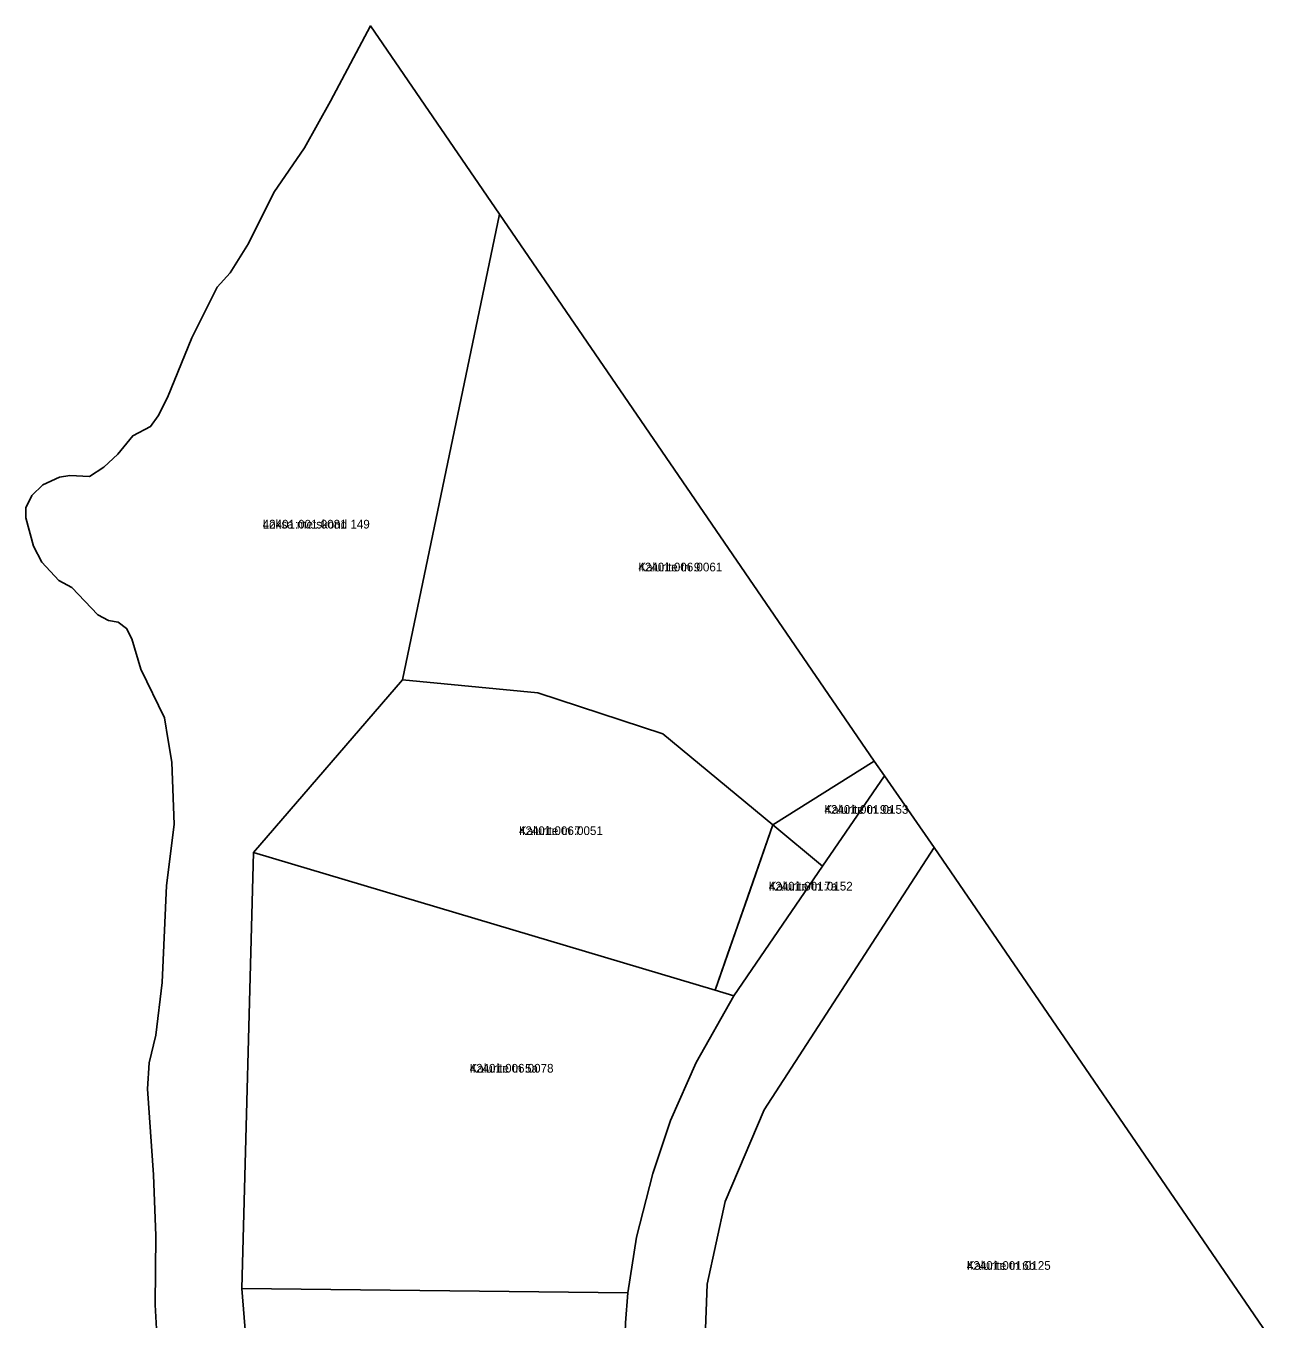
# Model space of a CAD drawing. Extents: x 595979 to 597983, y 6604231 to 6607350.
# Drawn here: x 596332.4 to 596548.3, y 6607126.6 to 6607350 of the extents above; entities that cross this region are included whole.
import ezdxf

# ---------------------------------------------------------------- set-up
doc = ezdxf.new("R2010")
doc.units = 0
for name, color, linetype in [('L_AADRESS', 7, 'Continuous'), ('PIIR', 7, 'Continuous'), ('TUNNUS', 7, 'Continuous')]:
    doc.layers.add(name, color=color, linetype=linetype)

msp = doc.modelspace()

# ---------------------------------------------------------------- linework, layer by layer
at = {"layer": 'PIIR'}
for points in [[(596355.78, 6607109.34), (596354.72, 6607129.05), (596354.85, 6607140.96), (596354.45, 6607151.54), (596353.4, 6607166.36), (596353.66, 6607170.86), (596354.85, 6607175.62), (596355.91, 6607184.75), (596356.65, 6607201.52), (596357.99, 6607212.07), (596357.59, 6607222.8), (596356.97, 6607226.55), (596356.33, 6607230.48), (596352.23, 6607238.88), (596350.69, 6607244.1), (596349.78, 6607245.93), (596348.29, 6607247.03), (596346.65, 6607247.32), (596344.8, 6607248.25), (596340.3, 6607253.01), (596338.05, 6607254.2), (596335.14, 6607257.38), (596333.69, 6607260.16), (596332.36, 6607265.05), (596332.36, 6607266.77), (596333.42, 6607268.89), (596335.27, 6607270.74), (596338.18, 6607272.06), (596339.98, 6607272.35), (596343.34, 6607272.19), (596345.85, 6607273.78), (596348.24, 6607276.03), (596350.83, 6607279.22), (596353.92, 6607280.79), (596355.25, 6607282.65), (596356.84, 6607285.82), (596361.07, 6607296.14), (596365.44, 6607304.87), (596367.68, 6607307.38), (596370.86, 6607312.41), (596375.22, 6607321.27), (596380.52, 6607328.95), (596385.01, 6607337.02), (596391.91, 6607350.04), (596414.22, 6607317.51), (596397.46, 6607237.04), (596371.73, 6607207.23), (596369.69, 6607131.86), (596375.64, 6607058.29)], [(596435.98, 6607125.93), (596436.42, 6607131.12), (596437.91, 6607140.77), (596440.71, 6607151.77), (596443.8, 6607160.91), (596448.2, 6607170.94), (596454.72, 6607182.46), (596470.04, 6607204.83), (596480.75, 6607220.47), (596489.35, 6607208.1), (596459.97, 6607162.74), (596453.22, 6607146.91), (596450.12, 6607132.65), (596449.44, 6607114.1)]]:
    msp.add_lwpolyline(points, dxfattribs=at)
for points in [[(596414.22, 6607317.51), (596479.01, 6607222.97), (596461.48, 6607211.99), (596442.45, 6607227.7), (596420.87, 6607234.78), (596397.46, 6607237.04)], [(596371.73, 6607207.23), (596397.46, 6607237.04), (596420.87, 6607234.78), (596442.45, 6607227.7), (596461.48, 6607211.99), (596451.51, 6607183.42)], [(596461.48, 6607211.99), (596479.01, 6607222.97), (596480.75, 6607220.47), (596470.04, 6607204.83)], [(596454.72, 6607182.46), (596451.51, 6607183.42), (596453.66, 6607189.58), (596457.08, 6607199.38), (596461.48, 6607211.99), (596470.04, 6607204.83)], [(596371.73, 6607207.23), (596451.51, 6607183.42), (596454.72, 6607182.46), (596448.2, 6607170.94), (596443.8, 6607160.91), (596440.71, 6607151.77), (596437.91, 6607140.77), (596436.42, 6607131.12), (596369.69, 6607131.86)], [(596489.35, 6607208.1), (596548.29, 6607122.04), (596541.96, 6607120.71), (596544.58, 6607065.45), (596522.96, 6607062.1), (596515.74, 6607110.18), (596452.37, 6607101.57), (596449.44, 6607114.1), (596450.12, 6607132.65), (596453.22, 6607146.91), (596459.97, 6607162.74)], [(596369.69, 6607131.86), (596436.42, 6607131.12), (596435.98, 6607125.93), (596435.8, 6607119.13), (596436.34, 6607110.82), (596438.26, 6607096.51), (596444.88, 6607066.02), (596408.99, 6607056.28), (596375.64, 6607058.29)]]:
    msp.add_lwpolyline(points, close=True, dxfattribs=at)

# ---------------------------------------------------------------- texts
at = {"layer": 'L_AADRESS'}
for s, p in [('Loksa metskond 149', (596373.29, 6607263.19)), ('Kalurite tn 9', (596438.23, 6607255.78)), ('Kalurite tn 9a', (596470.39, 6607213.9)), ('Kalurite tn 7', (596417.59, 6607210.23)), ('Kalurite tn 7a', (596460.77, 6607200.64)), ('Kalurite tn 5a', (596409.06, 6607169.18)), ('Kalurite tn 6b', (596495, 6607135.1))]:
    msp.add_text(s, height=1.5, dxfattribs=at).set_placement(p)
at = {"layer": 'TUNNUS'}
for s, p in [('42401:001:0081', (596373.29, 6607263.19)), ('42401:006:0061', (596438.23, 6607255.78)), ('42401:001:0153', (596470.39, 6607213.9)), ('42401:006:0051', (596417.59, 6607210.23)), ('42401:001:0152', (596460.77, 6607200.64)), ('42401:006:0078', (596409.06, 6607169.18)), ('42401:001:0125', (596495, 6607135.1))]:
    msp.add_text(s, height=1.5, dxfattribs=at).set_placement(p)

doc.saveas('drawing.dxf')
